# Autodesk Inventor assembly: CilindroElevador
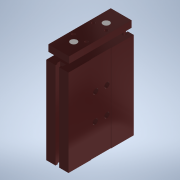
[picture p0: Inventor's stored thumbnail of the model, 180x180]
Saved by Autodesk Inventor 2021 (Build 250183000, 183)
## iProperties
Created: 2021-02
Part Number: CilindroElevador
Document SubType Name: Assembly
Designer: ATOUZA
Author: ATOUZA
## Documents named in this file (4)
- D:\01 Paralaia\Grupos de Traballo\GT Maquetas\CAD 3D\E_Medida\CilindroElevador.iam
- D:\01 Paralaia\Grupos de Traballo\GT Maquetas\CAD 3D\E_Medida\CuerpoCilindro.ipt
- D:\01 Paralaia\Grupos de Traballo\GT Maquetas\CAD 3D\E_Medida\vástago.ipt
- D:\01 Paralaia\Grupos de Traballo\GT Maquetas\CAD 3D\E_Medida\SoporteSuperior.ipt
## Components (4 placed, 3 different names)
1. CuerpoCilindro:1 — Insertar:1, Insertar:2, Ángulo:1
2. vástago:1 — Insertar:1, Nivelación:1, Coincidencia:2
3. vástago:2 — Insertar:2, Nivelación:1, Coincidencia:1
4. SoporteSuperior:1 — Coincidencia:1, Coincidencia:2, Ángulo:1
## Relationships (6: Insert 2, Mate 2, Flush 1, Angle 1)
- Insertar:1: CuerpoCilindro:1 ↔ vástago:1
- Insertar:2: CuerpoCilindro:1 ↔ vástago:2
- Nivelación:1 [Flush]: vástago:1 ↔ vástago:2
- Coincidencia:1 [Mate]: vástago:2 ↔ SoporteSuperior:1
- Coincidencia:2 [Mate]: vástago:1 ↔ SoporteSuperior:1
- Ángulo:1 [Angle]: CuerpoCilindro:1 ↔ SoporteSuperior:1
